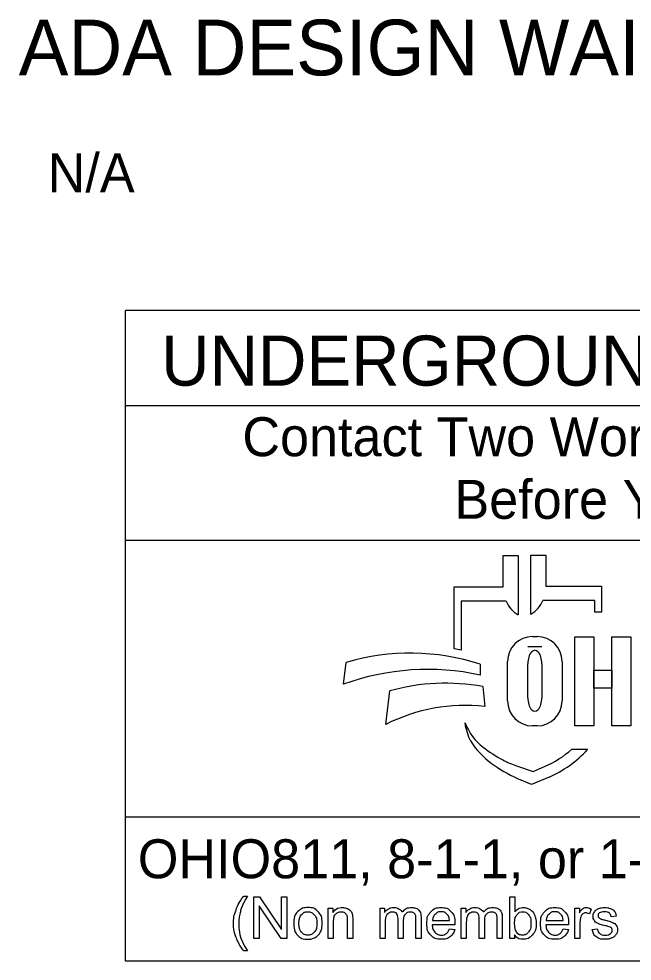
# Model space of a CAD drawing. Extents: x -8.2 to 38.5, y -0.1 to 21.9.
# Drawn here: x 2.058 to 4.26, y 2.007 to 5.393 of the extents above; entities that cross this region are included whole.
import ezdxf

# ---------------------------------------------------------------- set-up
doc = ezdxf.new("R2010")
doc.units = 0
doc.layers.add('GM_X_Adjacent_County', color=7, linetype='Continuous')
doc.layers.add('GM_X_Township', color=7, linetype='Continuous')

msp = doc.modelspace()

# ---------------------------------------------------------------- linework, layer by layer
at = {"layer": 'GM_X_Adjacent_County'}
for p, q in [((3.7969, 3.3528), (3.7969, 3.4643)), ((3.7969, 3.4643), (3.8506, 3.4643)), ((3.8506, 3.4643), (3.8506, 3.2522)), ((3.8962, 3.2545), (3.8962, 3.4666)), ((3.8962, 3.4666), (3.9499, 3.4666)), ((3.9499, 3.4666), (3.9499, 3.3551)), ((3.621, 3.1289), (3.621, 3.3528)), ((3.621, 3.3528), (3.7969, 3.3528)), ((3.9499, 3.3551), (4.1491, 3.3551)), ((4.1491, 3.3551), (4.1491, 3.2613)), ((3.6462, 3.3013), (3.6462, 3.1245)), ((3.8073, 3.3013), (3.6462, 3.3013)), ((4.1258, 3.3036), (3.9395, 3.3036)), ((4.1258, 3.2613), (4.1258, 3.3036)), ((4.1491, 3.2613), (4.1258, 3.2613)), ((3.9019, 3.1736), (3.9185, 3.1736)), ((3.9352, 3.1366), (3.8854, 3.1366)), ((3.8124, 2.9421), (3.8124, 3.0841)), ((4.0079, 3.0841), (4.0079, 2.9421)), ((3.2236, 3.0026), (3.233, 3.0807)), ((3.7143, 3.0742), (3.7143, 3.0354)), ((3.8854, 2.9535), (3.8854, 3.0758)), ((3.9351, 3.0758), (3.9351, 2.9535)), ((3.7242, 2.9936), (3.7305, 2.9226)), ((3.3754, 2.858), (3.3901, 2.9782)), ((3.6631, 2.8451), (3.6601, 2.8631)), ((3.9185, 2.8526), (3.9019, 2.8526)), ((4.0434, 2.7693), (4.1008, 2.7693)), ((3.845, 2.7089), (3.9044, 2.6884)), ((3.9044, 2.6884), (3.9454, 2.7062)), ((3.8984, 2.6414), (3.861, 2.6578)), ((3.9617, 2.6688), (3.8984, 2.6414))]:
    msp.add_line(p, q, dxfattribs=at)
for points in [[(4.0543, 3.1725), (4.1223, 3.1725), (4.1223, 2.8526), (4.0543, 2.8526)], [(4.1865, 3.1725), (4.2545, 3.1725), (4.2545, 2.8526), (4.1865, 2.8526)], [(4.1223, 3.0526), (4.1865, 3.0526), (4.1865, 2.9886), (4.1223, 2.9886)]]:
    msp.add_lwpolyline(points, close=True, dxfattribs=at)
for points in [[(2.8655, 2.2411), (2.8787, 2.2411)], [(2.9022, 2.0884), (2.9022, 2.2385), (2.9226, 2.2385), (3.0016, 2.1206), (3.0016, 2.2385), (3.0206, 2.2385), (3.0206, 2.0884), (3.0003, 2.0884), (2.9212, 2.2063), (2.9212, 2.0884), (2.9022, 2.0884)], [(3.8377, 2.0884), (3.8207, 2.0884), (3.8207, 2.2385), (3.8391, 2.2385), (3.8391, 2.185)], [(3.1682, 2.0884), (3.1682, 2.1972), (3.1848, 2.1972), (3.1848, 2.1818)], [(3.3546, 2.0884), (3.3546, 2.1972), (3.3711, 2.1972), (3.3711, 2.1819)], [(3.646, 2.0884), (3.646, 2.1972), (3.6625, 2.1972), (3.6625, 2.1819)], [(4.0538, 2.0884), (4.0538, 2.1972), (4.0704, 2.1972), (4.0704, 2.1807)], [(4.1128, 2.1937), (4.1064, 2.1767)], [(4.2028, 2.1691), (4.1847, 2.1667)], [(3.1866, 2.1478), (3.1866, 2.0884), (3.1682, 2.0884)], [(3.2566, 2.1553), (3.2566, 2.0884), (3.2381, 2.0884), (3.2381, 2.1545)], [(3.3731, 2.1448), (3.3731, 2.0884), (3.3546, 2.0884)], [(3.4377, 2.1516), (3.4377, 2.0884), (3.4193, 2.0884), (3.4193, 2.159)], [(3.5021, 2.1631), (3.5021, 2.0884), (3.4837, 2.0884), (3.4837, 2.1569)], [(3.6234, 2.1381), (3.5422, 2.1381)], [(3.5432, 2.1532), (3.604, 2.1532)], [(3.6644, 2.1448), (3.6644, 2.0884), (3.646, 2.0884)], [(3.7291, 2.1516), (3.7291, 2.0884), (3.7107, 2.0884), (3.7107, 2.159)], [(3.7935, 2.1631), (3.7935, 2.0884), (3.7751, 2.0884), (3.7751, 2.1569)], [(4.0314, 2.1381), (3.9502, 2.1381)], [(3.9512, 2.1532), (4.012, 2.1532)], [(4.0722, 2.1454), (4.0722, 2.0884), (4.0538, 2.0884)], [(3.6038, 2.1235), (3.6229, 2.1211)], [(3.8377, 2.102), (3.8377, 2.0884)], [(4.0118, 2.1235), (4.0308, 2.1211)], [(4.1164, 2.1209), (4.1346, 2.1238)], [(2.8787, 2.0442), (2.8655, 2.0442)]]:
    msp.add_lwpolyline(points, dxfattribs=at)
for centre, radius, start, end in [((3.8987, 3.3381), 0.0985, 201.9296, 240.7469), ((3.8481, 3.3404), 0.0985, 299.2531, 338.0704), ((3.9019, 3.0841), 0.0895, 90, 180), ((3.9185, 3.0841), 0.0895, 0, 90), ((3.4928, 2.3199), 0.8191, 79.2074, 81.0007), ((3.4631, 2.2946), 0.8191, 72.1402, 106.3144), ((3.5261, 2.1635), 0.8919, 77.8238, 109.8274), ((3.59, 2.2738), 0.7322, 79.44, 105.8467), ((3.6621, 2.2906), 0.6357, 83.8248, 116.8021), ((3.9019, 2.9421), 0.0895, 180, 270), ((3.9185, 2.9421), 0.0895, 270, 0), ((3.8474, 2.9352), 0.2008, 201.0457, 232.5314), ((3.8044, 2.8692), 0.1433, 189.6817, 216.0884), ((3.9381, 2.9667), 0.3088, 216.0884, 235.7167), ((4.04, 3.1864), 0.5173, 232.5314, 241.794), ((3.802, 3.0367), 0.3602, 293.4582, 312.0712), ((3.802, 3.0367), 0.401, 293.4582, 317.8286), ((4.1046, 3.2109), 0.6044, 235.7167, 246.2325), ((3.9548, 3.0276), 0.3371, 241.794, 250.9821)]:
    msp.add_arc(centre, radius, start, end, dxfattribs=at)
for centre, start_param, end_param in [((3.9103, 3.0758), 4.712389, 7.853982), ((3.9103, 2.9535), 1.570796, 4.712389)]:
    msp.add_ellipse(centre, major_axis=(0, 0.0484), ratio=0.514403, start_param=start_param, end_param=end_param, dxfattribs=at)
for points in [[(2.8655, 2.0442), (2.8502, 2.0635), (2.8397, 2.0893), (2.8291, 2.1151), (2.8291, 2.1427), (2.8291, 2.1671), (2.837, 2.1894), (2.8462, 2.2153), (2.8655, 2.2411)], [(2.8787, 2.2411), (2.8663, 2.2198), (2.8623, 2.2106), (2.8561, 2.1965), (2.8525, 2.1811), (2.8481, 2.162), (2.8481, 2.1426), (2.8481, 2.0934), (2.8787, 2.0442)], [(3.0447, 2.1428), (3.0447, 2.173), (3.0615, 2.1875), (3.0755, 2.1996), (3.0957, 2.1996), (3.1181, 2.1996), (3.1324, 2.1849), (3.1466, 2.1702), (3.1466, 2.1443), (3.1466, 2.1234), (3.1403, 2.1113), (3.134, 2.0993), (3.122, 2.0926), (3.1099, 2.086), (3.0957, 2.086), (3.0729, 2.086), (3.0588, 2.1006), (3.0447, 2.1153), (3.0447, 2.1428)], [(3.0637, 2.1428), (3.0637, 2.1219), (3.0728, 2.1115), (3.0819, 2.1011), (3.0957, 2.1011), (3.1094, 2.1011), (3.1185, 2.1115), (3.1276, 2.122), (3.1276, 2.1434), (3.1276, 2.1636), (3.1184, 2.174), (3.1093, 2.1844), (3.0957, 2.1844), (3.0819, 2.1844), (3.0728, 2.1741), (3.0637, 2.1637), (3.0637, 2.1428)], [(3.1848, 2.1818), (3.1968, 2.1996), (3.2194, 2.1996), (3.2292, 2.1996), (3.2375, 2.1961), (3.2457, 2.1926), (3.2498, 2.1868), (3.2539, 2.1811), (3.2555, 2.1732), (3.2566, 2.1681), (3.2566, 2.1553)], [(3.2381, 2.1545), (3.2381, 2.1658), (3.236, 2.1714), (3.2338, 2.177), (3.2284, 2.1803), (3.2229, 2.1836), (3.2155, 2.1836), (3.2037, 2.1836), (3.1952, 2.1761), (3.1866, 2.1687), (3.1866, 2.1478)], [(3.3711, 2.1819), (3.3762, 2.1899), (3.3847, 2.1948), (3.3932, 2.1996), (3.4041, 2.1996), (3.4162, 2.1996), (3.4239, 2.1946), (3.4317, 2.1896), (3.4348, 2.1805), (3.4478, 2.1996), (3.4685, 2.1996), (3.4847, 2.1996), (3.4934, 2.1907), (3.5021, 2.1817), (3.5021, 2.1631)], [(3.4193, 2.159), (3.4193, 2.1713), (3.4148, 2.1775), (3.4103, 2.1836), (3.4, 2.1836), (3.3922, 2.1836), (3.3856, 2.1795), (3.379, 2.1754), (3.376, 2.1675), (3.3731, 2.1596), (3.3731, 2.1448)], [(3.4837, 2.1569), (3.4837, 2.1679), (3.4819, 2.1728), (3.4801, 2.1777), (3.4754, 2.1806), (3.4707, 2.1836), (3.4644, 2.1836), (3.4529, 2.1836), (3.4453, 2.176), (3.4377, 2.1684), (3.4377, 2.1516)], [(3.6229, 2.1211), (3.6184, 2.1044), (3.6062, 2.0952), (3.594, 2.086), (3.575, 2.086), (3.5512, 2.086), (3.5372, 2.1007), (3.5232, 2.1154), (3.5232, 2.1419), (3.5232, 2.1693), (3.5374, 2.1845), (3.5515, 2.1996), (3.574, 2.1996), (3.5958, 2.1996), (3.6096, 2.1848), (3.6235, 2.1699), (3.6235, 2.143), (3.6235, 2.1413), (3.6234, 2.1381)], [(3.604, 2.1532), (3.6028, 2.1669), (3.597, 2.1738), (3.5882, 2.1845), (3.5742, 2.1845), (3.5615, 2.1845), (3.5528, 2.176), (3.5442, 2.1675), (3.5432, 2.1532)], [(3.6625, 2.1819), (3.6676, 2.1899), (3.6761, 2.1948), (3.6846, 2.1996), (3.6955, 2.1996), (3.7076, 2.1996), (3.7153, 2.1946), (3.723, 2.1896), (3.7262, 2.1805), (3.7391, 2.1996), (3.7599, 2.1996), (3.7761, 2.1996), (3.7848, 2.1907), (3.7935, 2.1817), (3.7935, 2.1631)], [(3.7107, 2.159), (3.7107, 2.1713), (3.7061, 2.1775), (3.7016, 2.1836), (3.6914, 2.1836), (3.6836, 2.1836), (3.677, 2.1795), (3.6704, 2.1754), (3.6674, 2.1675), (3.6644, 2.1596), (3.6644, 2.1448)], [(3.7751, 2.1569), (3.7751, 2.1679), (3.7733, 2.1728), (3.7715, 2.1777), (3.7668, 2.1806), (3.7621, 2.1836), (3.7557, 2.1836), (3.7442, 2.1836), (3.7367, 2.176), (3.7291, 2.1684), (3.7291, 2.1516)], [(3.8375, 2.1436), (3.8375, 2.1241), (3.8428, 2.1153), (3.8515, 2.1011), (3.8663, 2.1011), (3.8784, 2.1011), (3.8872, 2.1116), (3.896, 2.1221), (3.896, 2.1429), (3.896, 2.1642), (3.8875, 2.1744), (3.8791, 2.1845), (3.8671, 2.1845), (3.8551, 2.1845), (3.8463, 2.174), (3.8375, 2.1635), (3.8375, 2.1436)], [(3.8391, 2.185), (3.8508, 2.1996), (3.8689, 2.1996), (3.8789, 2.1996), (3.8879, 2.1956), (3.8968, 2.1915), (3.9026, 2.1842), (3.9084, 2.1769), (3.9117, 2.1666), (3.915, 2.1562), (3.915, 2.1444), (3.915, 2.1165), (3.9011, 2.1012), (3.8873, 2.086), (3.8679, 2.086), (3.8487, 2.086), (3.8377, 2.102)], [(4.0308, 2.1211), (4.0263, 2.1044), (4.0142, 2.0952), (4.002, 2.086), (3.983, 2.086), (3.9592, 2.086), (3.9452, 2.1007), (3.9312, 2.1154), (3.9312, 2.1419), (3.9312, 2.1693), (3.9453, 2.1845), (3.9595, 2.1996), (3.982, 2.1996), (4.0038, 2.1996), (4.0176, 2.1848), (4.0315, 2.1699), (4.0315, 2.143), (4.0315, 2.1413), (4.0314, 2.1381)], [(4.012, 2.1532), (4.0108, 2.1669), (4.005, 2.1738), (3.9962, 2.1845), (3.9822, 2.1845), (3.9695, 2.1845), (3.9608, 2.176), (3.9522, 2.1675), (3.9512, 2.1532)], [(4.0704, 2.1807), (4.0767, 2.1923), (4.0821, 2.196), (4.0875, 2.1996), (4.0939, 2.1996), (4.1032, 2.1996), (4.1128, 2.1937)], [(4.1064, 2.1767), (4.0997, 2.1806), (4.0929, 2.1806), (4.0869, 2.1806), (4.0821, 2.177), (4.0773, 2.1734), (4.0753, 2.1669), (4.0722, 2.1571), (4.0722, 2.1454)], [(4.1847, 2.1667), (4.1835, 2.1751), (4.1776, 2.1798), (4.1717, 2.1845), (4.1609, 2.1845), (4.1482, 2.1845), (4.1428, 2.1803), (4.1373, 2.1761), (4.1373, 2.1705), (4.1373, 2.1669), (4.1396, 2.164), (4.1418, 2.161), (4.1467, 2.1591), (4.1494, 2.158), (4.163, 2.1544), (4.1826, 2.1491), (4.1903, 2.1458), (4.1981, 2.1425), (4.2025, 2.1361), (4.2069, 2.1298), (4.2069, 2.1204), (4.2069, 2.1112), (4.2015, 2.103), (4.1961, 2.0949), (4.186, 2.0904), (4.1758, 2.086), (4.163, 2.086), (4.1417, 2.086), (4.1306, 2.0948), (4.1195, 2.1036), (4.1164, 2.1209)], [(4.1346, 2.1238), (4.1361, 2.1128), (4.1432, 2.1069), (4.1502, 2.1011), (4.1628, 2.1011), (4.1756, 2.1011), (4.1817, 2.1063), (4.1879, 2.1115), (4.1879, 2.1184), (4.1879, 2.1247), (4.1825, 2.1283), (4.1787, 2.1307), (4.1636, 2.1345), (4.1433, 2.1397), (4.1354, 2.1434), (4.1276, 2.1471), (4.1235, 2.1537), (4.1195, 2.1603), (4.1195, 2.1683), (4.1195, 2.1756), (4.1228, 2.1818), (4.1261, 2.188), (4.1319, 2.1921), (4.1362, 2.1952), (4.1436, 2.1974), (4.1511, 2.1996), (4.1596, 2.1996), (4.1724, 2.1996), (4.1821, 2.1959), (4.1918, 2.1922), (4.1964, 2.1859), (4.201, 2.1796), (4.2028, 2.1691)], [(3.5422, 2.1381), (3.5432, 2.1201), (3.5524, 2.1106), (3.5615, 2.1011), (3.5751, 2.1011), (3.5853, 2.1011), (3.5924, 2.1064), (3.5996, 2.1118), (3.6038, 2.1235)], [(3.9502, 2.1381), (3.9512, 2.1201), (3.9604, 2.1106), (3.9695, 2.1011), (3.9831, 2.1011), (3.9933, 2.1011), (4.0004, 2.1064), (4.0076, 2.1118), (4.0118, 2.1235)]]:
    msp.add_open_spline(points, degree=3, dxfattribs=at)
at = {"layer": 'GM_X_Township'}
for p, q in [((2.4409, 2.0073), (2.4409, 4.3448)), ((6.6909, 4.3448), (2.4409, 4.3448)), ((2.4409, 4.0032), (6.6909, 4.0032)), ((2.4409, 3.5198), (6.6909, 3.5198)), ((6.6909, 2.5251), (2.4409, 2.5251)), ((6.6909, 2.0073), (2.4409, 2.0073))]:
    msp.add_line(p, q, dxfattribs=at)

# ---------------------------------------------------------------- texts
at = {"layer": 'GM_X_Adjacent_County'}
for s, height, p in [('ADA DESIGN WAIVERS', 0.2, (2.0578, 5.1901)), ('  N/A                                    ', 0.14, (2.0578, 4.7701)), ('UNDERGROUND UTILITIES', 0.18, (2.569, 4.0751)), ('Contact Two Working Days', 0.14, (2.8605, 3.8216)), ('Before You Dig', 0.14, (3.6217, 3.5966)), ('OHIO811, 8-1-1, or 1-800-362-2764', 0.14, (2.4854, 2.3051))]:
    msp.add_text(s, height=height, dxfattribs=at).set_placement(p)

doc.saveas('drawing.dxf')
